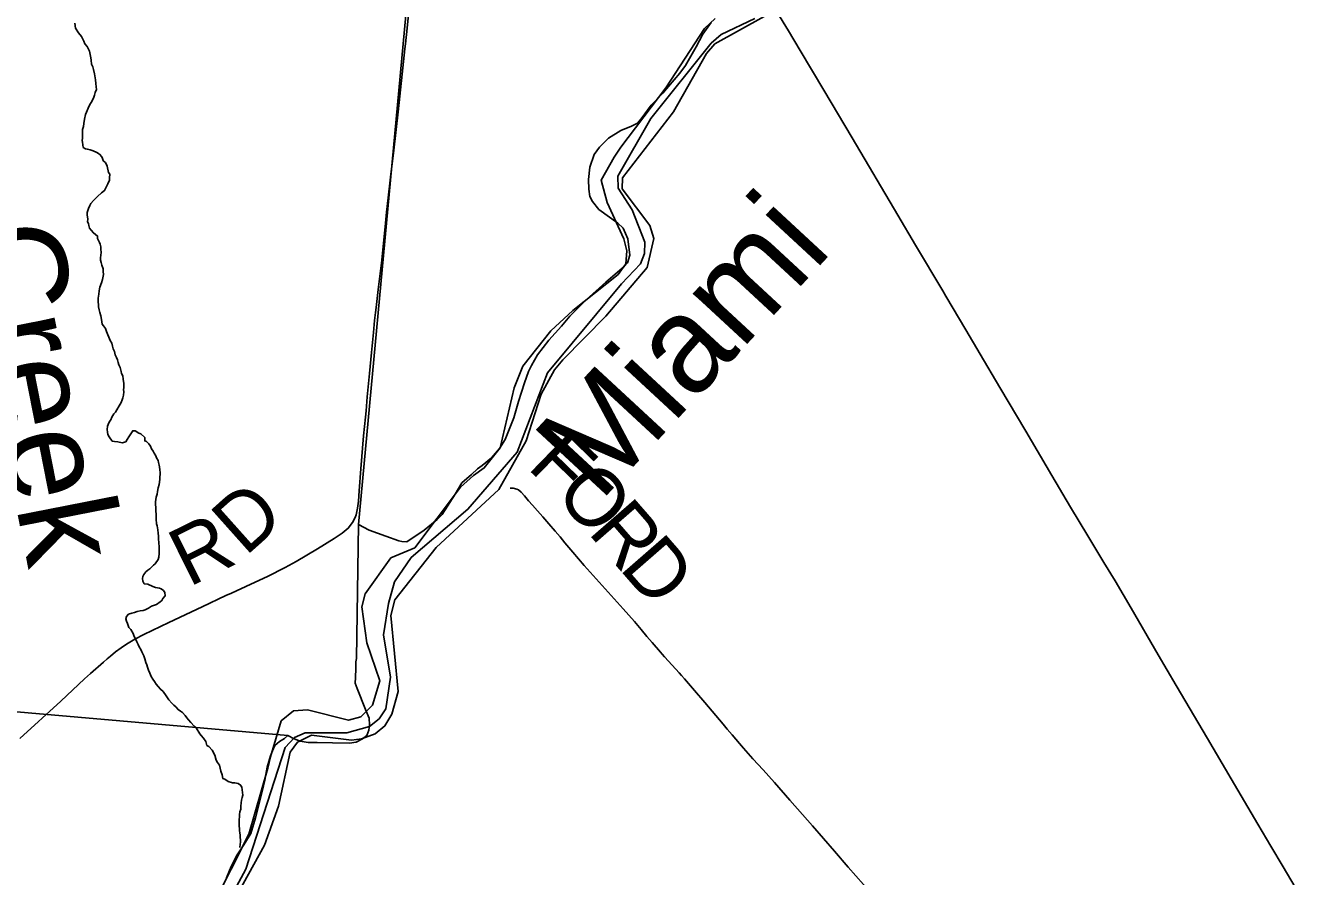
# Model space of a CAD drawing. Extents: x 1410790 to 1770854, y 448063 to 770588.
# Drawn here: x 1552911 to 1559596, y 626808 to 631210 of the extents above; entities that cross this region are included whole.
import ezdxf

# ---------------------------------------------------------------- set-up
doc = ezdxf.new("R2010")
doc.units = 0
for name, color, linetype in [('GM_X_County_Road', 7, 'Continuous'), ('GM_X_Major_River', 7, 'Continuous'), ('GM_X_Major_River_Text', 7, 'Continuous'), ('GM_X_Minor_River', 7, 'Continuous'), ('GM_X_Minor_River_Text', 7, 'Continuous'), ('GM_X_Section', 7, 'Continuous'), ('GM_X_Township', 7, 'Continuous'), ('GM_X_Township_Road', 7, 'Continuous'), ('GM_X_Township_Road_Text', 7, 'Continuous')]:
    doc.layers.add(name, color=color, linetype=linetype)

msp = doc.modelspace()

# ---------------------------------------------------------------- linework, layer by layer
at = {"layer": 'GM_X_County_Road'}
for points in [[(1556735.3, 631386.2), (1556796.7, 631281.5), (1556855.6, 631183.9), (1556917, 631082.1), (1557038.8, 630875.8), (1557184.9, 630630.6), (1557421.4, 630229), (1557513, 630073.6), (1557654.4, 629837.2), (1557670.4, 629810.2)], [(1557670.4, 629810.2), (1557773.1, 629636.7), (1557848, 629509.4), (1557949.7, 629337.1), (1558083.9, 629111.5), (1558219.2, 628882.6), (1558315.4, 628718.5), (1558405, 628569.5), (1558488.1, 628432), (1558545.1, 628336.2), (1558628.1, 628194.7), (1558768.9, 627953.9), (1558861.8, 627795.4), (1559023.4, 627521.2), (1559146.8, 627312.1), (1559284.6, 627077.2), (1559350.9, 626964), (1559414.4, 626856.8), (1559539.7, 626646.1), (1559595.9, 626549.7)]]:
    msp.add_lwpolyline(points, dxfattribs=at)
at = {"layer": 'GM_X_Major_River'}
for points in [[(1556476.5, 631247.3), (1556421.3, 631196.4), (1556222.4, 630888.2), (1555989.4, 630580.7), (1555954.2, 630529.3), (1555887.5, 630410.6), (1555919, 630295.7), (1556005, 630107.5), (1556019.7, 630045.1), (1556014.2, 629977.1), (1555974.9, 629921.9), (1555740.6, 629736.6), (1555626.2, 629630.9), (1555482, 629447.7), (1555437.5, 629336.5), (1555364.6, 629025.5), (1555282.2, 628921.1), (1555227.3, 628882.2), (1555159.9, 628821.6), (1554922.8, 628508.2), (1554799.5, 628456.7), (1554667.3, 628269.3), (1554649.8, 628201.5), (1554675.7, 628016.6), (1554741.5, 627818.9), (1554704.7, 627693.5), (1554643.3, 627632.7), (1554580.8, 627616), (1554367.8, 627668.7), (1554295.6, 627664.2), (1554232.4, 627611.5), (1554176.2, 627426.4), (1554162.9, 627366.6), (1554065.4, 627026.1), (1553881.1, 626659.4)], [(1556731, 631257.8), (1556475.7, 631117.1), (1556432.5, 631065.9), (1556261.7, 630765.1), (1555997.9, 630422.2), (1555996.7, 630366.2), (1556138.7, 630176.8), (1556159.2, 630108.2), (1556125.9, 629958.7), (1555912.1, 629706.9), (1555688.9, 629481.3), (1555645.7, 629428.2), (1555576.9, 629303.4), (1555499.5, 629060.7), (1555357.8, 628809.3), (1555032.9, 628509.8), (1554820.7, 628237.9), (1554799, 628158.2), (1554836.4, 627764.8), (1554803.8, 627647.2), (1554768.4, 627585.9), (1554717.4, 627544.9), (1554646.8, 627518.4), (1554596.6, 627511.5), (1554388.9, 627538), (1554316, 627501.5), (1554278.9, 627450.2), (1554218.7, 627171), (1554146.2, 626968.2), (1553925.2, 626568.3)]]:
    msp.add_lwpolyline(points, dxfattribs=at)
at = {"layer": 'GM_X_Minor_River'}
for points in [[(1553249.7, 631031), (1553247.8, 631043.1), (1553240, 631079.2), (1553228.2, 631103.3), (1553216.3, 631115.5), (1553210.4, 631129.5), (1553198.6, 631153.7), (1553182.8, 631173.9), (1553169, 631198), (1553165.2, 631224.1)], [(1553389.2, 629466.9), (1553385.3, 629481), (1553379.4, 629493.1), (1553373.5, 629507.2), (1553369.6, 629523.2), (1553363.7, 629537.3), (1553359.8, 629551.4), (1553356, 629567.4), (1553348.1, 629581.5), (1553328.4, 629627.8), (1553322.6, 629643.8), (1553312.7, 629655.9), (1553306.7, 629666), (1553302.9, 629690.1), (1553299.1, 629708.2), (1553293.2, 629726.3), (1553291.3, 629740.3), (1553287.4, 629754.3), (1553287.5, 629766.4), (1553285.6, 629778.4), (1553285.7, 629788.4), (1553285.8, 629800.4), (1553288, 629820.5), (1553290.1, 629838.5), (1553294.2, 629856.5), (1553302.4, 629878.5), (1553308.6, 629896.4), (1553312.8, 629922.4), (1553310.9, 629938.5), (1553311, 629952.5), (1553305.2, 629970.6), (1553301.3, 629984.7), (1553297.4, 629996.7), (1553297.5, 630006.7), (1553299.6, 630024.8), (1553301.7, 630034.8), (1553299.9, 630054.8), (1553299.9, 630064.8), (1553296, 630078.9), (1553292.1, 630088.9), (1553282.3, 630109.1), (1553282.4, 630121.1), (1553260.5, 630137.3), (1553248.6, 630151.4), (1553240.7, 630161.5), (1553236.8, 630175.6), (1553234.9, 630185.6), (1553230.9, 630195.7), (1553231.1, 630209.7), (1553229.2, 630231.8), (1553229.3, 630243.8), (1553235.5, 630263.8), (1553241.6, 630279.7), (1553247.7, 630289.7), (1553261.8, 630305.6), (1553282, 630325.5), (1553302.2, 630345.3), (1553318.3, 630357.2), (1553326.4, 630375.2), (1553334.6, 630391.1), (1553344.7, 630411.1), (1553344.8, 630423.1), (1553345, 630441.1), (1553339.1, 630451.2), (1553331.3, 630483.3), (1553323.4, 630501.4), (1553313.5, 630509.5), (1553303.7, 630531.7), (1553291.8, 630545.8), (1553277.8, 630553.9), (1553259.9, 630562.1), (1553243.9, 630568.2), (1553230, 630570.4), (1553220, 630572.4), (1553208, 630580.6), (1553204.2, 630606.7), (1553202.3, 630616.7), (1553204.4, 630628.7), (1553204.5, 630644.7), (1553204.6, 630658.7), (1553204.7, 630672.8), (1553208.9, 630688.8), (1553211, 630704.8), (1553215.2, 630726.8), (1553219.4, 630750.8), (1553225.5, 630762.8), (1553233.7, 630782.7), (1553241.8, 630802.7), (1553249.9, 630812.6), (1553262.1, 630834.6), (1553266.2, 630850.6), (1553270.3, 630864.5), (1553276.5, 630880.5), (1553274.6, 630894.6), (1553272.7, 630910.6), (1553270.9, 630930.7), (1553267.1, 630960.8), (1553261.3, 630982.8), (1553257.4, 630996.9), (1553251.5, 631011), (1553249.7, 631031)], [(1553623.8, 628286.7), (1553611.9, 628294.8), (1553601.9, 628298.9), (1553582, 628303.1), (1553568, 628307.2), (1553542.1, 628319.4), (1553524.1, 628321.6), (1553516.2, 628335.7), (1553514.3, 628349.8), (1553516.4, 628359.8), (1553522.4, 628369.7), (1553532.6, 628383.7), (1553542.6, 628391.6), (1553552.7, 628399.5), (1553570.9, 628417.4), (1553580.9, 628425.3), (1553595.1, 628447.2), (1553599.2, 628459.2), (1553601.4, 628479.2), (1553601.5, 628493.3), (1553601.6, 628507.3), (1553599.9, 628539.4), (1553597.9, 628549.4), (1553598.1, 628567.4), (1553596.2, 628583.5), (1553594.4, 628601.5), (1553590.5, 628621.6), (1553586.6, 628631.7), (1553584.8, 628655.7), (1553585, 628681.8), (1553583.1, 628697.8), (1553583.2, 628707.8), (1553583.3, 628717.8), (1553581.4, 628729.9), (1553581.5, 628745.9), (1553585.7, 628769.9), (1553589.8, 628785.9), (1553592, 628799.9), (1553596.1, 628817.9), (1553600.2, 628835.9), (1553602.3, 628847.9), (1553604.5, 628863.9), (1553604.6, 628876), (1553606.7, 628888), (1553606.7, 628898), (1553604.9, 628912), (1553603, 628926.1), (1553601, 628936.1), (1553597.2, 628950.2), (1553595.2, 628960.2), (1553587.3, 628974.3), (1553583.4, 628984.3), (1553575.5, 628998.4), (1553569.6, 629008.5), (1553561.7, 629020.6), (1553555.8, 629034.7), (1553547.9, 629046.8), (1553536, 629058.9), (1553526, 629061), (1553526.1, 629079), (1553506.3, 629097.2), (1553496.3, 629101.3), (1553476.4, 629113.5), (1553464.4, 629113.6), (1553454.3, 629097.7), (1553444.1, 629081.7), (1553436, 629067.8), (1553427.9, 629055.8), (1553409.9, 629052), (1553387.9, 629056.2), (1553369.9, 629058.3), (1553357.9, 629060.4), (1553342.1, 629082.6), (1553336.2, 629094.7), (1553334.3, 629106.7), (1553332.4, 629120.8), (1553334.5, 629136.8), (1553336.6, 629146.8), (1553344.7, 629160.8), (1553350.8, 629170.7), (1553356.9, 629184.7), (1553367, 629200.6), (1553375.1, 629210.6), (1553381.2, 629222.5), (1553393.4, 629242.5), (1553403.5, 629260.4), (1553409.6, 629274.4), (1553413.7, 629284.4), (1553415.8, 629298.4), (1553418, 629314.4), (1553416.1, 629326.4), (1553418.2, 629336.4), (1553418.2, 629348.5), (1553418.3, 629358.5), (1553414.5, 629380.6), (1553412.6, 629398.6), (1553406.7, 629410.7), (1553404.8, 629420.7), (1553399, 629440.8), (1553393.1, 629454.9), (1553389.2, 629466.9)], [(1554017.4, 626956.7), (1554019.5, 626974.7), (1554021.6, 626984.7), (1554019.9, 627020.8), (1554018, 627032.8), (1554016.1, 627042.9), (1554016.2, 627052.9), (1554014.3, 627068.9), (1554014.5, 627089), (1554014.6, 627101), (1554016.7, 627115), (1554016.8, 627127), (1554018.9, 627141), (1554023, 627155), (1554023.1, 627171), (1554025.3, 627187.1), (1554027.4, 627201.1), (1554029.5, 627215.1), (1554033.6, 627227.1), (1554029.8, 627255.2), (1554027.9, 627269.2), (1554022, 627279.3), (1554010.1, 627287.4), (1553992.1, 627291.6), (1553980.1, 627291.7), (1553958.1, 627297.9), (1553940.2, 627310), (1553930.2, 627314.1), (1553926.4, 627332.2), (1553920.5, 627352.3), (1553912.8, 627382.4), (1553902.9, 627396.5), (1553895, 627408.6), (1553889.2, 627434.7), (1553875.4, 627460.9), (1553857.5, 627479.1), (1553847.5, 627485.2), (1553841.7, 627505.3), (1553829.8, 627523.4), (1553817.9, 627535.5), (1553812, 627545.6), (1553792.2, 627575.8), (1553782.3, 627583.9), (1553764.4, 627604.2), (1553752.6, 627618.3), (1553744.6, 627628.4), (1553734.7, 627640.5), (1553720.8, 627654.6), (1553710.9, 627662.7), (1553698.9, 627670.8), (1553687, 627685), (1553677.1, 627693.1), (1553667.2, 627703.2), (1553651.3, 627721.4), (1553643.4, 627731.4), (1553637.5, 627741.5), (1553621.6, 627763.7), (1553607.7, 627775.8), (1553595.8, 627790), (1553585.9, 627802.1), (1553576, 627816.2), (1553568.1, 627828.3), (1553560.2, 627842.4), (1553552.4, 627858.5), (1553546.5, 627874.6), (1553540.6, 627890.7), (1553536.7, 627902.7), (1553532.8, 627914.8), (1553526.9, 627932.8), (1553521.1, 627948.9), (1553511.2, 627969.1), (1553505.3, 627981.1), (1553497.4, 627995.2), (1553491.5, 628007.3), (1553485.6, 628021.4), (1553479.7, 628033.4), (1553471.8, 628049.5), (1553466, 628063.6), (1553454.1, 628085.8), (1553444.2, 628095.9), (1553436.4, 628116), (1553432.4, 628128), (1553428.5, 628140.1), (1553432.6, 628152.1), (1553442.7, 628164), (1553458.8, 628169.9), (1553472.8, 628173.8), (1553486.9, 628177.7), (1553502.9, 628181.5), (1553518.9, 628183.4), (1553529, 628187.3), (1553545.1, 628195.2), (1553561.1, 628205.1), (1553577.2, 628210.9), (1553587.2, 628214.9), (1553605.4, 628228.7), (1553615.4, 628234.7), (1553619.5, 628244.6), (1553631.6, 628258.6), (1553629.8, 628276.6), (1553623.8, 628286.7)]]:
    msp.add_lwpolyline(points, dxfattribs=at)
at = {"layer": 'GM_X_Section'}
msp.add_lwpolyline([(1549719.6, 633308.3), (1555022.2, 632826.4), (1554631.8, 628627.9), (1554620.8, 627934.3), (1554618.6, 627918.3), (1554618, 627882.4), (1554617.3, 627836.4), (1554614.8, 627806.4), (1554624.4, 627780.3), (1554668.6, 627671.6), (1554687.9, 627625.3), (1554689.4, 627591.3), (1554684.9, 627563.4), (1554674.5, 627535.6), (1554652.2, 627519.9), (1554620, 627502.5), (1554585.9, 627497), (1554498, 627498.4), (1554418, 627499.6), (1554372, 627500.4), (1554330.2, 627507), (1554298.4, 627519.5), (1554266.6, 627536), (1549189.3, 627980.4)], close=True, dxfattribs=at)
for points in [[(1556456.4, 631226.2), (1556413.5, 631166.9), (1556378.5, 631101.5), (1556323, 631004.4), (1556294.4, 630964.8), (1556206.7, 630860.3), (1556145.8, 630799.2), (1556094.7, 630728.1), (1556074.3, 630706.4), (1556044.1, 630690.9), (1555989.7, 630667.7), (1555925.1, 630628.8), (1555878.4, 630581.5), (1555851.8, 630544), (1555828.8, 630478.4), (1555821.8, 630414.5), (1555823, 630364.5), (1555828.4, 630326.4), (1555842, 630300.2), (1555875.3, 630259.7), (1555974.1, 630188.2), (1556001.7, 630161.7), (1556024.8, 630107.4), (1556035.5, 630023.2), (1556022.9, 629983.4), (1556008.6, 629965.7), (1555911.3, 629883.3), (1555809.9, 629790.9), (1555724.6, 629706.3), (1555681.8, 629654.9), (1555616.6, 629582), (1555557.5, 629507), (1555526.6, 629451.5), (1555512.1, 629419.7), (1555491.2, 629362), (1555459.6, 629264.6), (1555436.3, 629181), (1555415.5, 629129.3), (1555390.5, 629067.7), (1555361.8, 629022.2), (1555319.1, 628972.9), (1555272.5, 628933.6), (1555248.2, 628916), (1555215.7, 628886.6), (1555167.1, 628843.4), (1555132.2, 628785.9), (1555093.2, 628722.6), (1555064.5, 628681), (1555038.1, 628653.5), (1554971.3, 628598.5), (1554882.3, 628538), (1554856.4, 628540.4), (1554840.4, 628544.6), (1554772.8, 628567.7), (1554687.3, 628599), (1554631.8, 628627.9), (1555022.2, 632826.4)], [(1549189.3, 627980.4), (1554266.6, 627536), (1554248.4, 627520.3), (1554224.2, 627504.7), (1554199.8, 627485.1), (1554187.4, 627457.3), (1554177, 627431.5), (1554160, 627371.8), (1554147, 627306), (1554136.2, 627254.2), (1554099.9, 627110.8), (1554074.6, 627029.3), (1554039.7, 626969.8), (1554004.9, 626918.4), (1553974, 626858.9), (1553949, 626799.3)]]:
    msp.add_lwpolyline(points, dxfattribs=at)
at = {"layer": 'GM_X_Township'}
for points in [[(1556681.9, 631247.6), (1556508.7, 631165), (1556456.2, 631119.4), (1556144, 630729.3), (1555972.9, 630432.2), (1555974.4, 630370), (1556047.6, 630257.1), (1556112.3, 630090.1), (1556111.8, 630031.9), (1556091.3, 629978), (1555992.1, 629874.7), (1555609.1, 629413.1), (1555453.1, 629003.6), (1555197.9, 628707.2), (1554905, 628457.4), (1554817.6, 628331.9), (1554786.6, 628219.9), (1554761.1, 628057.7), (1554797.3, 627838.8), (1554773.8, 627674.6), (1554739.3, 627622.8), (1554688.8, 627583.2), (1554572.2, 627550.2), (1554355.6, 627550.2), (1554301.3, 627526.7), (1554252.7, 627475), (1554048.7, 626845.3), (1553889.7, 626546)], [(1553889.7, 626546), (1554048.7, 626845.3), (1554252.7, 627475), (1554301.3, 627526.7), (1554355.6, 627550.2), (1554572.2, 627550.2), (1554688.8, 627583.2), (1554739.3, 627622.8), (1554773.8, 627674.6), (1554797.3, 627838.8), (1554761.1, 628057.7), (1554786.6, 628219.9), (1554817.6, 628331.9), (1554905, 628457.4), (1555197.9, 628707.2), (1555453.1, 629003.6), (1555609.1, 629413.1), (1555992.1, 629874.7), (1556091.3, 629978), (1556111.8, 630031.9), (1556112.3, 630090.1), (1556047.6, 630257.1), (1555974.4, 630370), (1555972.9, 630432.2), (1556144, 630729.3), (1556456.2, 631119.4), (1556508.7, 631165), (1556681.9, 631247.6)]]:
    msp.add_lwpolyline(points, dxfattribs=at)
at = {"layer": 'GM_X_Township_Road'}
for points in [[(1552879.9, 627520.3), (1553092.2, 627713.3), (1553214.9, 627829), (1553245.2, 627857.3), (1553312.9, 627916.6), (1553332.7, 627933.9), (1553348.6, 627947.6), (1553375.8, 627969.5), (1553405, 627990.8), (1553432.4, 628009.2), (1553474.6, 628034.5), (1553521, 628058.4), (1553650.7, 628121.4), (1553822.9, 628202.7), (1553946.5, 628260.8), (1553975, 628273.9), (1554074.6, 628319.9), (1554160.9, 628359.9), (1554252.1, 628405.7), (1554309.5, 628437.8), (1554419.5, 628503.3), (1554506.9, 628555.5), (1554548.2, 628582.9), (1554578.6, 628608.8), (1554601.3, 628638.2), (1554614.8, 628665.1), (1554619.6, 628677.7), (1554627.6, 628713.4), (1554631.3, 628749.8), (1554635.3, 628802.4), (1554643.6, 628917), (1554657.9, 629086.8), (1554667.8, 629184.7), (1554670.9, 629217.4), (1554677.6, 629289.2), (1554688.9, 629410.1), (1554698.8, 629518), (1554709.2, 629622.5), (1554715.1, 629684.1), (1554719.6, 629725.9), (1554723, 629750.9), (1554734.3, 629845.3), (1554752.3, 629995.8), (1554761.4, 630084.6), (1554769.3, 630169.4), (1554777.2, 630244.4), (1554785.4, 630319.3), (1554798, 630426.2), (1554815.4, 630565.3), (1554837.1, 630764.2), (1554857.4, 630959.8), (1554871.8, 631089.7), (1554874.5, 631115.5), (1554883.6, 631196.9), (1554896.6, 631319.7)], [(1556623.1, 627471.5), (1556603.6, 627495.7), (1556565.3, 627540), (1556539.8, 627569.9), (1556518, 627594.3), (1556422.6, 627707), (1556369.6, 627769.5), (1556318.3, 627829), (1556303.5, 627846.4), (1556290.2, 627860.8), (1556235, 627921.3), (1556215.3, 627943.2), (1556202.1, 627957.8), (1556193.4, 627967.6), (1556150.6, 628017.2), (1556123.3, 628049.6), (1556094.3, 628084.4), (1556059.3, 628126.2), (1556000.6, 628192.4), (1555907.5, 628295.7), (1555799.7, 628416.7), (1555741.4, 628484.6), (1555699.9, 628533.9), (1555674.8, 628563.8), (1555649.4, 628593.8), (1555617.3, 628631.2), (1555585.3, 628668.2), (1555557.6, 628699.8), (1555532.2, 628728.5), (1555511.3, 628751.8), (1555490, 628776.5), (1555473, 628795.2), (1555459.1, 628807.1), (1555450.5, 628811.9), (1555432.5, 628815.7), (1555416.2, 628816.7)], [(1558377.8, 625496.3), (1558306.8, 625559), (1558275.2, 625587.5), (1558241.5, 625623.2), (1558071.1, 625818.4), (1557926.7, 625984), (1557751.7, 626183.8), (1557628.1, 626328.4), (1557516, 626456.9), (1557431.5, 626552.9), (1557379.4, 626611.8), (1557333.9, 626663.4), (1557284, 626719.9), (1557165.2, 626855.6), (1557094.5, 626937.5), (1556980.5, 627068.7), (1556928.3, 627127.5), (1556863.6, 627201.6), (1556784.6, 627293.6), (1556724.5, 627358.7), (1556671.1, 627416.3), (1556623.8, 627470.7), (1556623.1, 627471.5)]]:
    msp.add_lwpolyline(points, dxfattribs=at)

# ---------------------------------------------------------------- texts
at = {"layer": 'GM_X_Major_River_Text'}
msp.add_text('Miami', height=499.94, rotation=47.18444, dxfattribs=at).set_placement((1555878.9, 628738.6))
at = {"layer": 'GM_X_Minor_River_Text'}
msp.add_text('Creek', height=499.9, rotation=281.10658, dxfattribs=at).set_placement((1552581.5, 630143.1))
at = {"layer": 'GM_X_Township_Road_Text'}
for s, rotation, p in [('F', 315.84668, (1555499.2, 628922.7)), ('O', 311.17462, (1555640, 628786.4)), ('D', 41.74871, (1554046.2, 628459.7)), ('R', 311.0365, (1555813.7, 628587.8)), ('R', 26.44636, (1553754.5, 628301.9)), ('D', 311.09484, (1555975.7, 628401.7))]:
    msp.add_text(s, height=300, rotation=rotation, dxfattribs=at).set_placement(p)

doc.saveas('drawing.dxf')
